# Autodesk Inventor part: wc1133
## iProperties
Shininess: 64.0
Length Units: 11272
Angle Units: 11279
Time Units: 11290
Mass Units: 11286
Length Display Precision: 3
Angle Display Precision: 2
Compacted: True
Part Number: wc1133
Document SubType Name: Modeling
Created: 2004-08
Designer: John Blackburn
Manufacturer: Standard
Standards Organization: Custom
Material: Aluminum-6061
Density: 0.0
Volumn: 0.0
Area: 0.0
PropertySet Name: Model Information
Control State: 0
Master: False
Checked Out: False
Author: John Blackburn
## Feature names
1. Base1
